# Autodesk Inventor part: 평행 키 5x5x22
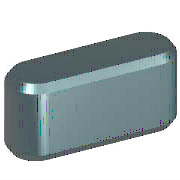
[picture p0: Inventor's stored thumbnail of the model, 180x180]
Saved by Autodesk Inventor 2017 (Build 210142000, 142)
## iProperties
IsCustomPart: 1
Created: 2012-02
Part Number: 평행 키 5x5x22
Material: 강철, 연강
Description: 평행 키
Document SubType Name: Modeling
Standard: JIS B 1301
Designer: mdu-01
Standards Organization: JIS
Language: ko-KR
Size Designation: 5x5x22
Categories: <MemberInstance><Categories><Category DisplayName="샤프트 부품" InternalName="7f7aeb1f-a693-4053-b835-cee3144e0d98" Mnemonic="SHFT"><Category DisplayName="키" Interna
Density: 1 g/cm^3
Appearance: 강철
Author: mdu-01
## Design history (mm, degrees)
workplane "Work Plane1"
workplane "Work Plane2"
sketch "스케치1"
  geometry: L1 (2.5, 2.5)-(19.5, 2.5); L2 (19.5, -2.5)-(2.5, -2.5); L3 (0, 9.4)-(0, -7.4) reference; L4 (-5, 0)-(30, 0) reference; L5 (22, 0)-(22, 7); A1 r 2.5 centre (2.5, 0) between (2.5, 2.5) and (2.5, -2.5); A2 r 2.5 centre (19.5, 0) between (19.5, -2.5) and (19.5, 2.5)
  constraints: 6 end point, 5 point on circle, 4 tangent, 3 point on line, 2 centre point, 1 horizontal, 1 parallel, 1 perpendicular
  dimensions: "d0" = 2.5 radius of A1 (= 0.5 x PB); "d13" = 2.5 radius of A2 (= 0.5 x PB); "d14" = 22 distance between parallel lines of L5 L3 (= NLG)
extrude "본체1" new body sketch "스케치1" taper "d3" = 0 deg; stored distance "d4" = 10
workplane "Work Plane3"
body "Solid1"
chamfer "모따기1" distance "d8" = 0.4 (= PHH); stored, may be unused: second distance "d9" = 0.4 (= PHH), angle "d15" = 45 deg
other parameters: "d1" = -3 (= -PNT), "d2" = 2 (= PH - PNT), "NLG" = 22 [user parameter; used in 3 equation terms], "PB" = 5 [user parameter; used in 2 equation terms], "PNT" = 3 [user parameter; used in 2 equation terms], "PH" = 5 [user parameter; used in 1 equation term], "PHH" = 0.4 [user parameter; used in 2 equation terms], "d10" = 0, "d16" = 0, "d17" = 0, "d18" = 0, "WDMIN" = 12 [user parameter], "PLB2" = 22 (= NLG) [user parameter], "WDMAX" = 17 [user parameter], "PLB1" = 22 (= NLG) [user parameter], "RR" = 0.16 [user parameter], "PUEB" = 2.3 [user parameter]
